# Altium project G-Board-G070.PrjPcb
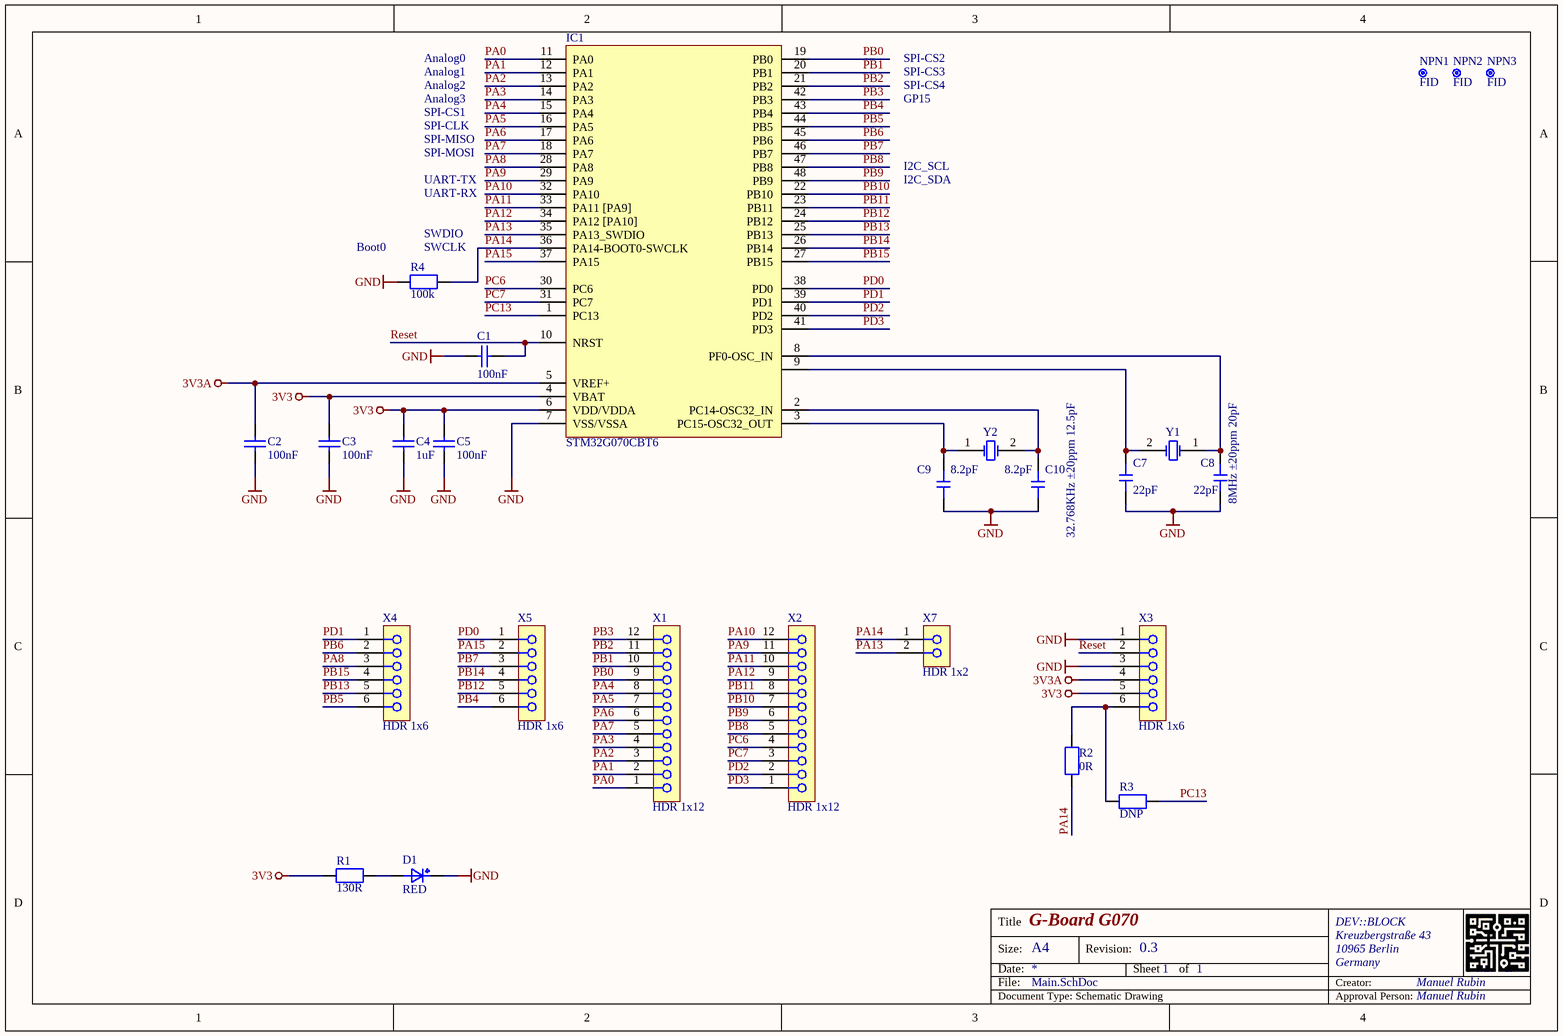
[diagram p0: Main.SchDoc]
address2: Kreuzbergstraße 43; address3: 10965 Berlin; address4: Germany; ApprovalSchematic: Manuel Rubin; CompanyName: DEV::BLOCK; CreatorSchematic: Manuel Rubin; ProjectRevision: 0.3
1 sheet, 26 parts. Net scope: global (net labels, ports and power ports of the same name join across sheets).
Board file: erb-pcb0004.PcbDoc

## Sheet Main.SchDoc: G-Board G070
size A4; Author: Manuel Koch; DrawnBy: Manuel Koch; DocumentNumber: erb-pcb0001; Revision: 0.1; SheetNumber: 1; SheetTotal: 1

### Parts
C1  100nF  [CAPC1005X55]
C2  100nF  [CAPC1005X55]
C3  100nF  [CAPC1005X55]
C4  1uF  [CAPC1005X55]
C5  100nF  [CAPC1005X55]
C7  22pF  [CAPC1608X95N]
C8  22pF  [CAPC1608X95N]
C9  8.2pF  [CAPC1608X95N]
C10  8.2pF  [CAPC1608X95N]
D1  RED  [WL-SMCW_0805]
IC1  STM32G070CBT6  [LQFP-48_7x7x05P]
NPN1  FID  [Fiducial_1mm]
NPN2  FID  [Fiducial_1mm]
NPN3  FID  [Fiducial_1mm]
R1  130R  [RESC2012X70N]
R2  0R  [RESC1608X55N]
R3  DNP  [RESC1608X55N]  (no BOM)
R4  100k  [RESC1005X40N]
X1  HDR 1x12  [61301211121_no]
X2  HDR 1x12  [61301211121_no]
X3  HDR 1x6  [61300611121_no]
X4  HDR 1x6  [61300611121_no]
X5  HDR 1x6  [61300611121_no]
X7  HDR 1x2  [CON_HEADER2.54_1x2W_no]
Y1  8MHz ±20ppm 20pF  [SMD-5032_2P]
Y2  32.768KHz ±20ppm 12.5pF  [SMD-3215_2P FC - 135]

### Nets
3V3: C3.2 C4.2 C5.2 IC1.4(VBAT) IC1.6(VDD/VDDA) R1.1 X3.5
3V3A: C2.2 IC1.5(VREF+) X3.4
GND: C1.2 C2.1 C3.1 C4.1 C5.1 C7.2 C8.2 C9.1 C10.1 D1.K IC1.7(VSS/VSSA) R4.2 X3.1 X3.3
PA0: IC1.11(PA0) X1.1
PA1: IC1.12(PA1) X1.2
PA2: IC1.13(PA2) X1.3
PA3: IC1.14(PA3) X1.4
PA4: IC1.15(PA4) X1.8
PA5: IC1.16(PA5) X1.7
PA6: IC1.17(PA6) X1.6
PA7: IC1.18(PA7) X1.5
PA8: IC1.28(PA8) X4.3
PA9: IC1.29(PA9) X2.11
PA10: IC1.32(PA10) X2.12
PA11: IC1.33(PA11_[PA9]) X2.10
PA12: IC1.34(PA12_[PA10]) X2.9
PA13: IC1.35(PA13_SWDIO) X7.2
PA14: IC1.36(PA14-BOOT0-SWCLK) R2.1 R4.1 X7.1
PA15: IC1.37(PA15) X5.2
PB0: IC1.19(PB0) X1.9
PB1: IC1.20(PB1) X1.10
PB2: IC1.21(PB2) X1.11
PB3: IC1.42(PB3) X1.12
PB4: IC1.43(PB4) X5.6
PB5: IC1.44(PB5) X4.6
PB6: IC1.45(PB6) X4.2
PB7: IC1.46(PB7) X5.3
PB8: IC1.47(PB8) X2.5
PB9: IC1.48(PB9) X2.6
PB10: IC1.22(PB10) X2.7
PB11: IC1.23(PB11) X2.8
PB12: IC1.24(PB12) X5.5
PB13: IC1.25(PB13) X4.5
PB14: IC1.26(PB14) X5.4
PB15: IC1.27(PB15) X4.4
PC6: IC1.30(PC6) X2.4
PC7: IC1.31(PC7) X2.3
PC13: IC1.1(PC13) R3.2
PD0: IC1.38(PD0) X5.1
PD1: IC1.39(PD1) X4.1
PD2: IC1.40(PD2) X2.2
PD3: IC1.41(PD3) X2.1
Reset: C1.1 IC1.10(NRST) X3.2
NetC7_1: C7.1 IC1.9(PF1-OSC_OU'T) Y1.2(OSC2)
NetC8_1: C8.1 IC1.8(PF0-OSC_IN) Y1.1(OSC1)
NetC9_2: C9.2 IC1.3(PC15-OSC32_OUT) Y2.1(OSC1)
NetC10_2: C10.2 IC1.2(PC14-OSC32_IN) Y2.2(OSC2)
NetD1_A: D1.A R1.2
NetR2_2: R2.2 R3.1 X3.6

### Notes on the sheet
- Analog0
- Analog1
- Analog2
- Analog3
- SPI-CS1
- SPI-CS2
- SPI-CS3
- SPI-CS4
- GP15
- SPI-CLK
- SPI-MOSI
- SPI-MISO
- I2C_SCL
- (near R4) Boot0
- UART-TX
- UART-RX
- (near R4) SWDIO
- (near R4) SWCLK
- I2C_SDA

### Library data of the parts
C1-C3 C5 = CAP_100nF_0402: X7R 100nF ±10% 16V 0402 Multilayer Ceramic Capacitors MLCC - SMD/SMT ROHS; Manufacturer: Samsung Electro-Mechanics; Manufacturer Part Number: CL05B104KO5NNNC; Voltage Rating: 16VDC; Alternatives allowed: yes
C4 = CAP_1uF_0402: X5R 25V ±10% 1uF 0402 Multilayer Ceramic Capacitors MLCC - SMD/SMT ROHS; Manufacturer: Samsung Electro-Mechanics; Manufacturer Part Number: CL05A105KA5NQNC; Alternatives allowed: yes
C7 C8 = CAP_22pF_50V_0603: Chip capacitors; Manufacturer: Samsung Electro-Mechanics; Manufacturer Part Number: CL10C220JB8NNNC; Voltage Rating: 50V; Alternatives allowed: YES; Notes: C0G, 0402
C9 C10 = CAP_8p2_50V_0603: Multilayer Ceramic Capacitors MLCC - SMD/SMT 0402 8.0pF 50volts C0G +/-0.5pF; Manufacturer: Guangdong Fenghua Advanced Tech; Manufacturer Part Number: 0603CG8R2C500NT; Voltage Rating: 50V; Alternatives allowed: YES; Notes: C0G, 0402
D1 = LED_0805_RED_AK: Standard LEDs - SMD WL-SMCW SMDMono TpVw Waterclr 0805 Red; Manufacturer: Wurth Elektronik; Manufacturer Part Number: 150080RS75000; Voltage Rating: 2.0; Alternatives allowed: YES
IC1 = STM32G070CBT6: ARM Mikrocontroller - MCU Mainstream Value line, Arm Cortex-M0+ MCU 128 Kbytes of Flash 36 Kbytes RAM, 64; Manufacturer: STMicroelectronics
NPN1-NPN3 = Fiducial_1mm
R1 = RES_130R_0805: Dickfilmwiderstände - SMD 1/8watt 130ohms 1% 100ppm; Manufacturer: Vishay / Dale; Manufacturer Part Number: CRCW0805130RFKEA; Voltage Rating: 150V; Alternatives allowed: YES
R2 = RES_0R_0603: Thick Film Resistors - SMD 1/10watt ZEROohm Jumper; Manufacturer: Vishay; Manufacturer Part Number: CRCW06030000Z0EA; Voltage Rating: 75V; Tolerance: 1%; Alternatives allowed: YES
R3 = RES_DNF_0603: Resistor SMD 0603 - not populated
R4 = RES_100k_0402: Thick Film Resistors - SMD 63mW 100Kohms 1%; Manufacturer: Vishay; Manufacturer Part Number: RC0402FR-07100KL; Voltage Rating: 50V; Alternatives allowed: YES
X1 X2 = CON_HEADER_1X12_no_overlay: Board-to-Board-Steckverbinder, 2.54 mm, 12 Kontakt(e), Stiftleiste 1-Reihig; Manufacturer: WE; Manufacturer Part Number: 61301211121; Alternatives allowed: YES
X3-X5 = CON_HEADER_1X6_no_overlay: Board-to-Board-Steckverbinder, 2.54 mm, 6 Kontakt(e), Stiftleiste 1-Reihig; Manufacturer: WE; Manufacturer Part Number: 61300611121; Alternatives allowed: YES
X7 = CON_HEADER_1X2_no_overlay: Board-to-Board-Steckverbinder, 2.54 mm, 2 Kontakt(e), Stiftleiste 1-Reihig; Manufacturer: Samtec; Manufacturer Part Number: TSW-102-07-T-S; Lumira Part Number: S-QMS-SPEC-32507; Alternatives allowed: YES
Y1 = SMD-5032_2P 8MHz 20ppm 20pF: 8MHz SMD Crystal Resonator 20pF ±10ppm ±50ppm -40℃~+85℃ SMD5032-2P Crystals ROHS; Manufacturer: Yangxing Tech; Manufacturer Part Number: X50328MSB2GI
Y2 = SMD-3215_2P 32.768KHz 20ppm 12.5pF: 32.768kHz SMD Crystal Resonator 12.5pF 70kΩ ±20ppm -40℃~+85℃ SMD3215-2P Crystals ROHS; Manufacturer: Seiko Epson; Manufacturer Part Number: Q13FC1350000400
